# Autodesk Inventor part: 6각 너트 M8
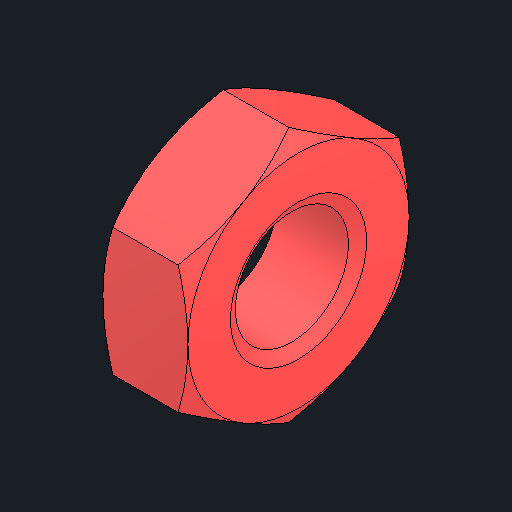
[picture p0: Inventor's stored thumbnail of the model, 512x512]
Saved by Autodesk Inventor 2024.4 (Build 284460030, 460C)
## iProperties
Created: 2026-08
Part Number: 6각 너트 M8
Material: 강철, 연강
Description: 6각 너트
Document SubType Name: Modeling
Designer: user
Density: 7.85 g/cm^3
Appearance: 기본값
Author: jhkim
Sending System: Autodesk Inventor 2027
Preprocessor: ST-DEVELOPER v20.1
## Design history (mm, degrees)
feature "Solid1"
node "솔리드1"
